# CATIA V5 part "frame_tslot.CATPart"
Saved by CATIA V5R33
Part number: frame_tslot
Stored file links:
  C:\Users\Ryzen5700u\Desktop\robot_cicloidale_singolo\Assieme_robot_cicloidale_singolo\frame_tslot.CATPart

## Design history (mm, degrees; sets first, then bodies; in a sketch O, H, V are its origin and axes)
Body1 "Solido1" (main body)
  Solid1: solid without history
